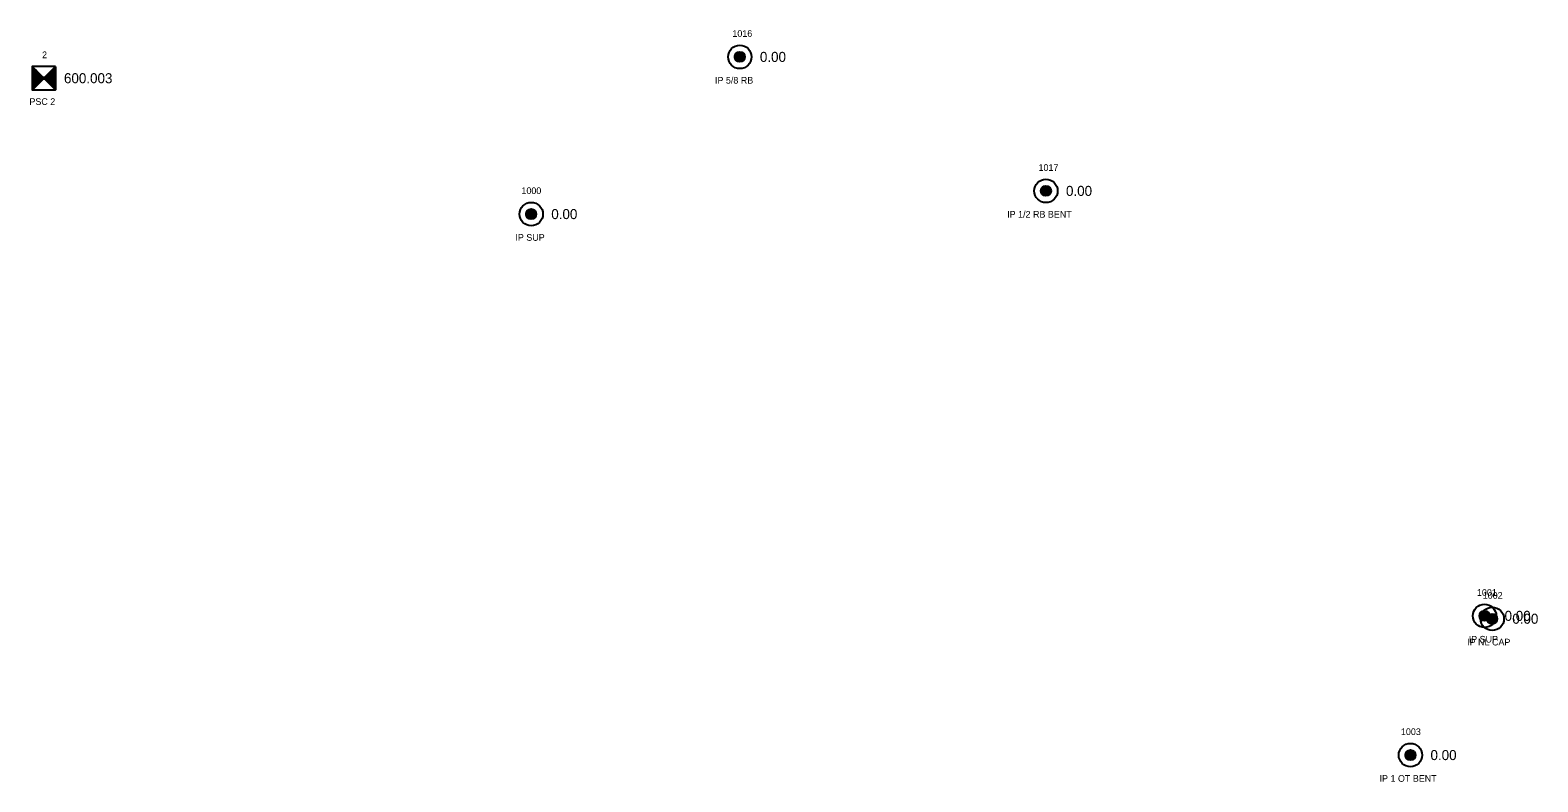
# Model space of a CAD drawing. Extents: x 1664393 to 1667175, y 987029 to 988607.
# Drawn here: x 1666338.4 to 1666564, y 987295.3 to 987407.9 of the extents above; entities that cross this region are included whole.
import ezdxf

# ---------------------------------------------------------------- set-up
doc = ezdxf.new("R2010")
doc.units = 0
for name, color, linetype in [('RD_EX_DV_Prop_txCode', 7, 'Continuous'), ('RD_EX_DV_PropPin', 7, 'Continuous'), ('RD_EX_TX_DV_Prop_ELEV', 7, 'Continuous'), ('RD_HC_Survey', 7, 'Continuous'), ('RD_HC_Survey_ELEV', 7, 'Continuous'), ('RD_HC_txCode', 7, 'Continuous'), ('RD_SMD_Locator', 7, 'Continuous')]:
    doc.layers.add(name, color=color, linetype=linetype)

msp = doc.modelspace()

# ---------------------------------------------------------------- linework, layer by layer
at = {"layer": 'RD_EX_DV_PropPin'}
for p, q in [((1666443.89, 987403.66), (1666443.89, 987404.05)), ((1666443.92, 987403.56), (1666443.92, 987404.15)), ((1666443.96, 987403.49), (1666443.96, 987404.23)), ((1666443.99, 987403.43), (1666443.99, 987404.28)), ((1666444.03, 987403.38), (1666444.03, 987404.33)), ((1666444.06, 987403.34), (1666444.06, 987404.37)), ((1666444.1, 987403.31), (1666444.1, 987404.41)), ((1666444.13, 987403.27), (1666444.13, 987404.44)), ((1666444.17, 987403.25), (1666444.17, 987404.47)), ((1666444.2, 987403.22), (1666444.2, 987404.49)), ((1666444.24, 987403.2), (1666444.24, 987404.51)), ((1666444.27, 987403.18), (1666444.27, 987404.53)), ((1666444.31, 987403.16), (1666444.31, 987404.55)), ((1666444.34, 987403.15), (1666444.34, 987404.56)), ((1666444.38, 987403.14), (1666444.38, 987404.58)), ((1666444.41, 987403.13), (1666444.41, 987404.59)), ((1666444.45, 987403.12), (1666444.45, 987404.6)), ((1666444.48, 987403.11), (1666444.48, 987404.6)), ((1666444.52, 987403.1), (1666444.52, 987404.61)), ((1666444.55, 987403.1), (1666444.55, 987404.61)), ((1666444.59, 987403.1), (1666444.59, 987404.62)), ((1666444.62, 987403.1), (1666444.62, 987404.62)), ((1666444.66, 987403.1), (1666444.66, 987404.62)), ((1666444.69, 987403.1), (1666444.69, 987404.61)), ((1666444.73, 987403.1), (1666444.73, 987404.61)), ((1666444.76, 987403.11), (1666444.76, 987404.6)), ((1666444.8, 987403.12), (1666444.8, 987404.6)), ((1666444.83, 987403.13), (1666444.83, 987404.59)), ((1666444.87, 987403.14), (1666444.87, 987404.58)), ((1666444.9, 987403.15), (1666444.9, 987404.56)), ((1666444.94, 987403.16), (1666444.94, 987404.55)), ((1666444.97, 987403.18), (1666444.97, 987404.53)), ((1666445.01, 987403.2), (1666445.01, 987404.51)), ((1666445.04, 987403.22), (1666445.04, 987404.49)), ((1666445.08, 987403.25), (1666445.08, 987404.47)), ((1666445.11, 987403.27), (1666445.11, 987404.44)), ((1666445.15, 987403.31), (1666445.15, 987404.41)), ((1666445.18, 987403.34), (1666445.18, 987404.37)), ((1666445.22, 987403.38), (1666445.22, 987404.33)), ((1666445.25, 987403.43), (1666445.25, 987404.28)), ((1666445.29, 987403.49), (1666445.29, 987404.23)), ((1666445.32, 987403.56), (1666445.32, 987404.15)), ((1666445.36, 987403.66), (1666445.36, 987404.05)), ((1666489.69, 987383.59), (1666489.69, 987383.98)), ((1666489.73, 987383.49), (1666489.73, 987384.08)), ((1666489.76, 987383.42), (1666489.76, 987384.15)), ((1666489.8, 987383.36), (1666489.8, 987384.21)), ((1666489.83, 987383.31), (1666489.83, 987384.26)), ((1666489.87, 987383.27), (1666489.87, 987384.3)), ((1666489.9, 987383.23), (1666489.9, 987384.34)), ((1666489.94, 987383.2), (1666489.94, 987384.37)), ((1666489.97, 987383.18), (1666489.97, 987384.4)), ((1666490.01, 987383.15), (1666490.01, 987384.42)), ((1666490.04, 987383.13), (1666490.04, 987384.44)), ((1666490.08, 987383.11), (1666490.08, 987384.46)), ((1666490.11, 987383.09), (1666490.11, 987384.48)), ((1666490.15, 987383.08), (1666490.15, 987384.49)), ((1666490.18, 987383.06), (1666490.18, 987384.51)), ((1666490.22, 987383.05), (1666490.22, 987384.52)), ((1666490.25, 987383.04), (1666490.25, 987384.53)), ((1666490.29, 987383.04), (1666490.29, 987384.53)), ((1666490.32, 987383.03), (1666490.32, 987384.54)), ((1666490.36, 987383.03), (1666490.36, 987384.54)), ((1666490.39, 987383.03), (1666490.39, 987384.55)), ((1666490.43, 987383.02), (1666490.43, 987384.55)), ((1666490.46, 987383.03), (1666490.46, 987384.55)), ((1666490.5, 987383.03), (1666490.5, 987384.54)), ((1666490.53, 987383.03), (1666490.53, 987384.54)), ((1666490.57, 987383.04), (1666490.57, 987384.53)), ((1666490.6, 987383.04), (1666490.6, 987384.53)), ((1666490.64, 987383.05), (1666490.64, 987384.52)), ((1666490.67, 987383.06), (1666490.67, 987384.51)), ((1666490.71, 987383.08), (1666490.71, 987384.49)), ((1666490.74, 987383.09), (1666490.74, 987384.48)), ((1666490.78, 987383.11), (1666490.78, 987384.46)), ((1666490.81, 987383.13), (1666490.81, 987384.44)), ((1666490.85, 987383.15), (1666490.85, 987384.42)), ((1666490.88, 987383.18), (1666490.88, 987384.4)), ((1666490.92, 987383.2), (1666490.92, 987384.37)), ((1666490.95, 987383.23), (1666490.95, 987384.34)), ((1666490.99, 987383.27), (1666490.99, 987384.3)), ((1666491.02, 987383.31), (1666491.02, 987384.26)), ((1666491.06, 987383.36), (1666491.06, 987384.21)), ((1666491.09, 987383.42), (1666491.09, 987384.15)), ((1666491.13, 987383.49), (1666491.13, 987384.08)), ((1666491.16, 987383.59), (1666491.16, 987383.98)), ((1666412.66, 987380.12), (1666412.66, 987380.51)), ((1666412.7, 987380.02), (1666412.7, 987380.61)), ((1666412.73, 987379.95), (1666412.73, 987380.69)), ((1666412.77, 987379.89), (1666412.77, 987380.74)), ((1666412.8, 987379.84), (1666412.8, 987380.79)), ((1666412.84, 987379.8), (1666412.84, 987380.83)), ((1666412.87, 987379.77), (1666412.87, 987380.87)), ((1666412.91, 987379.73), (1666412.91, 987380.9)), ((1666412.94, 987379.71), (1666412.94, 987380.93)), ((1666412.98, 987379.68), (1666412.98, 987380.95)), ((1666413.01, 987379.66), (1666413.01, 987380.97)), ((1666413.05, 987379.64), (1666413.05, 987380.99)), ((1666413.08, 987379.62), (1666413.08, 987381.01)), ((1666413.12, 987379.61), (1666413.12, 987381.02)), ((1666413.15, 987379.6), (1666413.15, 987381.04)), ((1666413.19, 987379.58), (1666413.19, 987381.05)), ((1666413.22, 987379.58), (1666413.22, 987381.06)), ((1666413.26, 987379.57), (1666413.26, 987381.06)), ((1666413.29, 987379.56), (1666413.29, 987381.07)), ((1666413.33, 987379.56), (1666413.33, 987381.07)), ((1666413.36, 987379.56), (1666413.36, 987381.08)), ((1666413.4, 987379.55), (1666413.4, 987381.08)), ((1666413.43, 987379.56), (1666413.43, 987381.08)), ((1666413.47, 987379.56), (1666413.47, 987381.07)), ((1666413.5, 987379.56), (1666413.5, 987381.07)), ((1666413.54, 987379.57), (1666413.54, 987381.06)), ((1666413.57, 987379.58), (1666413.57, 987381.06)), ((1666413.61, 987379.58), (1666413.61, 987381.05)), ((1666413.64, 987379.6), (1666413.64, 987381.04)), ((1666413.68, 987379.61), (1666413.68, 987381.02)), ((1666413.71, 987379.62), (1666413.71, 987381.01)), ((1666413.75, 987379.64), (1666413.75, 987380.99)), ((1666413.78, 987379.66), (1666413.78, 987380.97)), ((1666413.82, 987379.68), (1666413.82, 987380.95)), ((1666413.85, 987379.71), (1666413.85, 987380.93)), ((1666413.89, 987379.73), (1666413.89, 987380.9)), ((1666413.92, 987379.77), (1666413.92, 987380.87)), ((1666413.96, 987379.8), (1666413.96, 987380.83)), ((1666413.99, 987379.84), (1666413.99, 987380.79)), ((1666414.03, 987379.89), (1666414.03, 987380.74)), ((1666414.06, 987379.95), (1666414.06, 987380.69)), ((1666414.1, 987380.02), (1666414.1, 987380.61)), ((1666414.13, 987380.12), (1666414.13, 987380.51)), ((1666555.34, 987319.94), (1666555.34, 987320.33)), ((1666555.37, 987319.84), (1666555.37, 987320.43)), ((1666555.41, 987319.77), (1666555.41, 987320.51)), ((1666555.44, 987319.71), (1666555.44, 987320.56)), ((1666555.48, 987319.66), (1666555.48, 987320.61)), ((1666555.51, 987319.62), (1666555.51, 987320.65)), ((1666555.55, 987319.59), (1666555.55, 987320.69)), ((1666555.58, 987319.55), (1666555.58, 987320.72)), ((1666555.62, 987319.53), (1666555.62, 987320.75)), ((1666555.65, 987319.5), (1666555.65, 987320.77)), ((1666555.69, 987319.48), (1666555.69, 987320.79)), ((1666555.72, 987319.46), (1666555.72, 987320.81)), ((1666555.76, 987319.44), (1666555.76, 987320.83)), ((1666555.79, 987319.43), (1666555.79, 987320.84)), ((1666555.83, 987319.42), (1666555.83, 987320.86)), ((1666555.86, 987319.4), (1666555.86, 987320.87)), ((1666555.9, 987319.4), (1666555.9, 987320.88)), ((1666555.93, 987319.39), (1666555.93, 987320.88)), ((1666555.97, 987319.38), (1666555.97, 987320.89)), ((1666556, 987319.38), (1666556, 987320.89)), ((1666556.04, 987319.38), (1666556.04, 987320.9)), ((1666556.07, 987319.37), (1666556.07, 987320.9)), ((1666556.11, 987319.38), (1666556.11, 987320.9)), ((1666556.14, 987319.38), (1666556.14, 987320.89)), ((1666556.18, 987319.38), (1666556.18, 987320.89)), ((1666556.21, 987319.39), (1666556.21, 987320.88)), ((1666556.25, 987319.4), (1666556.25, 987320.88)), ((1666556.28, 987319.4), (1666556.28, 987320.87)), ((1666556.32, 987319.42), (1666556.32, 987320.86)), ((1666556.35, 987319.43), (1666556.35, 987320.84)), ((1666556.39, 987319.44), (1666556.39, 987320.83)), ((1666556.42, 987319.46), (1666556.42, 987320.81)), ((1666556.46, 987319.48), (1666556.46, 987320.79)), ((1666556.49, 987319.5), (1666556.49, 987320.77)), ((1666556.49, 987319.51), (1666556.49, 987319.9)), ((1666556.52, 987319.41), (1666556.52, 987320)), ((1666556.53, 987319.53), (1666556.53, 987320.75)), ((1666556.56, 987319.55), (1666556.56, 987320.72)), ((1666556.56, 987319.34), (1666556.56, 987320.07)), ((1666556.59, 987319.28), (1666556.59, 987320.13)), ((1666556.6, 987319.59), (1666556.6, 987320.69)), ((1666556.63, 987319.62), (1666556.63, 987320.65)), ((1666556.63, 987319.23), (1666556.63, 987320.18)), ((1666556.66, 987319.19), (1666556.66, 987320.22)), ((1666556.67, 987319.66), (1666556.67, 987320.61)), ((1666556.7, 987319.71), (1666556.7, 987320.56)), ((1666556.7, 987319.15), (1666556.7, 987320.26)), ((1666556.73, 987319.12), (1666556.73, 987320.29)), ((1666556.74, 987319.77), (1666556.74, 987320.51)), ((1666556.77, 987319.84), (1666556.77, 987320.43)), ((1666556.77, 987319.1), (1666556.77, 987320.31)), ((1666556.8, 987319.07), (1666556.8, 987320.34)), ((1666556.81, 987319.94), (1666556.81, 987320.33)), ((1666556.84, 987319.05), (1666556.84, 987320.36)), ((1666556.87, 987319.03), (1666556.87, 987320.38)), ((1666556.91, 987319.01), (1666556.91, 987320.4)), ((1666556.94, 987319), (1666556.94, 987320.41)), ((1666556.98, 987318.98), (1666556.98, 987320.43)), ((1666557.01, 987318.97), (1666557.01, 987320.44)), ((1666557.05, 987318.96), (1666557.05, 987320.45)), ((1666557.08, 987318.96), (1666557.08, 987320.45)), ((1666557.12, 987318.95), (1666557.12, 987320.46)), ((1666557.15, 987318.95), (1666557.15, 987320.46)), ((1666557.19, 987318.94), (1666557.19, 987320.47)), ((1666557.22, 987318.94), (1666557.22, 987320.47)), ((1666557.26, 987318.94), (1666557.26, 987320.47)), ((1666557.29, 987318.95), (1666557.29, 987320.46)), ((1666557.33, 987318.95), (1666557.33, 987320.46)), ((1666557.36, 987318.96), (1666557.36, 987320.45)), ((1666557.4, 987318.96), (1666557.4, 987320.45)), ((1666557.43, 987318.97), (1666557.43, 987320.44)), ((1666557.47, 987318.98), (1666557.47, 987320.43)), ((1666557.5, 987319), (1666557.5, 987320.41)), ((1666557.54, 987319.01), (1666557.54, 987320.4)), ((1666557.57, 987319.03), (1666557.57, 987320.38)), ((1666557.61, 987319.05), (1666557.61, 987320.36)), ((1666557.64, 987319.07), (1666557.64, 987320.34)), ((1666557.68, 987319.1), (1666557.68, 987320.31)), ((1666557.71, 987319.12), (1666557.71, 987320.29)), ((1666557.75, 987319.15), (1666557.75, 987320.26)), ((1666557.78, 987319.19), (1666557.78, 987320.22)), ((1666557.82, 987319.23), (1666557.82, 987320.18)), ((1666557.85, 987319.28), (1666557.85, 987320.13)), ((1666557.89, 987319.34), (1666557.89, 987320.07)), ((1666557.92, 987319.41), (1666557.92, 987320)), ((1666557.96, 987319.51), (1666557.96, 987319.9)), ((1666544.25, 987299.1), (1666544.25, 987299.49)), ((1666544.28, 987298.99), (1666544.28, 987299.59)), ((1666544.32, 987298.92), (1666544.32, 987299.66)), ((1666544.35, 987298.86), (1666544.35, 987299.72)), ((1666544.39, 987298.82), (1666544.39, 987299.77)), ((1666544.42, 987298.78), (1666544.42, 987299.81)), ((1666544.46, 987298.74), (1666544.46, 987299.84)), ((1666544.49, 987298.71), (1666544.49, 987299.87)), ((1666544.53, 987298.68), (1666544.53, 987299.9)), ((1666544.56, 987298.66), (1666544.56, 987299.93)), ((1666544.6, 987298.63), (1666544.6, 987299.95)), ((1666544.63, 987298.62), (1666544.63, 987299.97)), ((1666544.67, 987298.6), (1666544.67, 987299.98)), ((1666544.7, 987298.58), (1666544.7, 987300)), ((1666544.74, 987298.57), (1666544.74, 987300.01)), ((1666544.77, 987298.56), (1666544.77, 987300.02)), ((1666544.81, 987298.55), (1666544.81, 987300.03)), ((1666544.84, 987298.54), (1666544.84, 987300.04)), ((1666544.88, 987298.54), (1666544.88, 987300.05)), ((1666544.91, 987298.53), (1666544.91, 987300.05)), ((1666544.95, 987298.53), (1666544.95, 987300.05)), ((1666544.98, 987298.53), (1666544.98, 987300.05)), ((1666545.02, 987298.53), (1666545.02, 987300.05)), ((1666545.05, 987298.53), (1666545.05, 987300.05)), ((1666545.09, 987298.54), (1666545.09, 987300.05)), ((1666545.12, 987298.54), (1666545.12, 987300.04)), ((1666545.16, 987298.55), (1666545.16, 987300.03)), ((1666545.19, 987298.56), (1666545.19, 987300.02)), ((1666545.23, 987298.57), (1666545.23, 987300.01)), ((1666545.26, 987298.58), (1666545.26, 987300)), ((1666545.3, 987298.6), (1666545.3, 987299.98)), ((1666545.33, 987298.62), (1666545.33, 987299.97)), ((1666545.37, 987298.63), (1666545.37, 987299.95)), ((1666545.4, 987298.66), (1666545.4, 987299.93)), ((1666545.44, 987298.68), (1666545.44, 987299.9)), ((1666545.47, 987298.71), (1666545.47, 987299.87)), ((1666545.51, 987298.74), (1666545.51, 987299.84)), ((1666545.54, 987298.78), (1666545.54, 987299.81)), ((1666545.58, 987298.82), (1666545.58, 987299.77)), ((1666545.61, 987298.86), (1666545.61, 987299.72)), ((1666545.65, 987298.92), (1666545.65, 987299.66)), ((1666545.68, 987298.99), (1666545.68, 987299.59)), ((1666545.72, 987299.1), (1666545.72, 987299.49))]:
    msp.add_line(p, q, dxfattribs=at)
for centre, radius in [((1666444.62, 987403.86), 1.75), ((1666444.62, 987403.86), 0.761), ((1666490.43, 987383.79), 1.75), ((1666490.43, 987383.79), 0.761), ((1666413.4, 987380.32), 1.75), ((1666413.4, 987380.32), 0.761), ((1666556.07, 987320.14), 1.75), ((1666556.07, 987320.14), 0.761), ((1666557.22, 987319.7), 1.75), ((1666557.22, 987319.7), 0.761), ((1666544.98, 987299.29), 1.75), ((1666544.98, 987299.29), 0.761)]:
    msp.add_circle(centre, radius, dxfattribs=at)
at = {"layer": 'RD_HC_Survey'}
for p, q in [((1666338.72, 987402.42), (1666342.22, 987398.92)), ((1666342.22, 987402.42), (1666338.72, 987398.92)), ((1666338.75, 987402.39), (1666338.75, 987398.94)), ((1666338.77, 987402.37), (1666338.77, 987398.97)), ((1666338.8, 987402.34), (1666338.8, 987398.99)), ((1666338.82, 987402.32), (1666338.82, 987399.02)), ((1666338.85, 987402.29), (1666338.85, 987399.04)), ((1666338.87, 987402.27), (1666338.87, 987399.06)), ((1666338.9, 987402.24), (1666338.9, 987399.09)), ((1666338.92, 987402.22), (1666338.92, 987399.11)), ((1666338.95, 987402.19), (1666338.95, 987399.14)), ((1666338.97, 987402.17), (1666338.97, 987399.16)), ((1666338.99, 987402.14), (1666338.99, 987399.19)), ((1666339.02, 987402.12), (1666339.02, 987399.21)), ((1666339.04, 987402.09), (1666339.04, 987399.24)), ((1666339.07, 987402.07), (1666339.07, 987399.26)), ((1666339.09, 987402.04), (1666339.09, 987399.29)), ((1666339.12, 987402.02), (1666339.12, 987399.31)), ((1666339.14, 987402), (1666339.14, 987399.34)), ((1666339.17, 987401.97), (1666339.17, 987399.36)), ((1666339.19, 987401.95), (1666339.19, 987399.39)), ((1666339.22, 987401.92), (1666339.22, 987399.41)), ((1666339.24, 987401.9), (1666339.24, 987399.44)), ((1666339.27, 987401.87), (1666339.27, 987399.46)), ((1666339.29, 987401.85), (1666339.29, 987399.49)), ((1666339.32, 987401.82), (1666339.32, 987399.51)), ((1666339.34, 987401.8), (1666339.34, 987399.53)), ((1666339.37, 987401.77), (1666339.37, 987399.56)), ((1666339.39, 987401.75), (1666339.39, 987399.58)), ((1666339.42, 987401.72), (1666339.42, 987399.61)), ((1666339.44, 987401.7), (1666339.44, 987399.63)), ((1666339.47, 987401.67), (1666339.47, 987399.66)), ((1666339.49, 987401.65), (1666339.49, 987399.68)), ((1666339.51, 987401.62), (1666339.51, 987399.71)), ((1666339.54, 987401.6), (1666339.54, 987399.73)), ((1666339.56, 987401.57), (1666339.56, 987399.76)), ((1666339.59, 987401.55), (1666339.59, 987399.78)), ((1666339.61, 987401.53), (1666339.61, 987399.81)), ((1666339.64, 987401.5), (1666339.64, 987399.83)), ((1666339.66, 987401.48), (1666339.66, 987399.86)), ((1666339.69, 987401.45), (1666339.69, 987399.88)), ((1666339.71, 987401.43), (1666339.71, 987399.91)), ((1666339.74, 987401.4), (1666339.74, 987399.93)), ((1666339.76, 987401.38), (1666339.76, 987399.96)), ((1666339.79, 987401.35), (1666339.79, 987399.98)), ((1666339.81, 987401.33), (1666339.81, 987400.01)), ((1666339.84, 987401.3), (1666339.84, 987400.03)), ((1666339.86, 987401.28), (1666339.86, 987400.05)), ((1666339.89, 987401.25), (1666339.89, 987400.08)), ((1666339.91, 987401.23), (1666339.91, 987400.1)), ((1666339.94, 987401.2), (1666339.94, 987400.13)), ((1666339.96, 987401.18), (1666339.96, 987400.15)), ((1666339.98, 987401.15), (1666339.98, 987400.18)), ((1666340.01, 987401.13), (1666340.01, 987400.2)), ((1666340.03, 987401.1), (1666340.03, 987400.23)), ((1666340.06, 987401.08), (1666340.06, 987400.25)), ((1666340.08, 987401.05), (1666340.08, 987400.28)), ((1666340.11, 987401.03), (1666340.11, 987400.3)), ((1666340.13, 987401.01), (1666340.13, 987400.33)), ((1666340.16, 987400.98), (1666340.16, 987400.35)), ((1666340.18, 987400.96), (1666340.18, 987400.38)), ((1666340.21, 987400.93), (1666340.21, 987400.4)), ((1666340.23, 987400.91), (1666340.23, 987400.43)), ((1666340.26, 987400.88), (1666340.26, 987400.45)), ((1666340.28, 987400.86), (1666340.28, 987400.48)), ((1666340.31, 987400.83), (1666340.31, 987400.5)), ((1666340.33, 987400.81), (1666340.33, 987400.52)), ((1666340.36, 987400.78), (1666340.36, 987400.55)), ((1666340.38, 987400.76), (1666340.38, 987400.57)), ((1666340.41, 987400.73), (1666340.41, 987400.6)), ((1666340.54, 987400.73), (1666340.54, 987400.6)), ((1666340.56, 987400.76), (1666340.56, 987400.57)), ((1666340.59, 987400.78), (1666340.59, 987400.55)), ((1666340.61, 987400.81), (1666340.61, 987400.52)), ((1666340.64, 987400.83), (1666340.64, 987400.5)), ((1666340.66, 987400.86), (1666340.66, 987400.48)), ((1666340.69, 987400.88), (1666340.69, 987400.45)), ((1666340.71, 987400.91), (1666340.71, 987400.43)), ((1666340.74, 987400.93), (1666340.74, 987400.4)), ((1666340.76, 987400.96), (1666340.76, 987400.38)), ((1666340.79, 987400.98), (1666340.79, 987400.35)), ((1666340.81, 987401.01), (1666340.81, 987400.33)), ((1666340.84, 987401.03), (1666340.84, 987400.3)), ((1666340.86, 987401.05), (1666340.86, 987400.28)), ((1666340.89, 987401.08), (1666340.89, 987400.25)), ((1666340.91, 987401.1), (1666340.91, 987400.23)), ((1666340.94, 987401.13), (1666340.94, 987400.2)), ((1666340.96, 987401.15), (1666340.96, 987400.18)), ((1666340.99, 987401.18), (1666340.99, 987400.15)), ((1666341.01, 987401.2), (1666341.01, 987400.13)), ((1666341.03, 987401.23), (1666341.03, 987400.1)), ((1666341.06, 987401.25), (1666341.06, 987400.08)), ((1666341.08, 987401.28), (1666341.08, 987400.05)), ((1666341.11, 987401.3), (1666341.11, 987400.03)), ((1666341.13, 987401.33), (1666341.13, 987400.01)), ((1666341.16, 987401.35), (1666341.16, 987399.98)), ((1666341.18, 987401.38), (1666341.18, 987399.96)), ((1666341.21, 987401.4), (1666341.21, 987399.93)), ((1666341.23, 987401.43), (1666341.23, 987399.91)), ((1666341.26, 987401.45), (1666341.26, 987399.88)), ((1666341.28, 987401.48), (1666341.28, 987399.86)), ((1666341.31, 987401.5), (1666341.31, 987399.83)), ((1666341.33, 987401.53), (1666341.33, 987399.81)), ((1666341.36, 987401.55), (1666341.36, 987399.78)), ((1666341.38, 987401.57), (1666341.38, 987399.76)), ((1666341.41, 987401.6), (1666341.41, 987399.73)), ((1666341.43, 987401.62), (1666341.43, 987399.71)), ((1666341.46, 987401.65), (1666341.46, 987399.68)), ((1666341.48, 987401.67), (1666341.48, 987399.66)), ((1666341.5, 987401.7), (1666341.5, 987399.63)), ((1666341.53, 987401.72), (1666341.53, 987399.61)), ((1666341.55, 987401.75), (1666341.55, 987399.58)), ((1666341.58, 987401.77), (1666341.58, 987399.56)), ((1666341.6, 987401.8), (1666341.6, 987399.53)), ((1666341.63, 987401.82), (1666341.63, 987399.51)), ((1666341.65, 987401.85), (1666341.65, 987399.49)), ((1666341.68, 987401.87), (1666341.68, 987399.46)), ((1666341.7, 987401.9), (1666341.7, 987399.44)), ((1666341.73, 987401.92), (1666341.73, 987399.41)), ((1666341.75, 987401.95), (1666341.75, 987399.39)), ((1666341.78, 987401.97), (1666341.78, 987399.36)), ((1666341.8, 987402), (1666341.8, 987399.34)), ((1666341.83, 987402.02), (1666341.83, 987399.31)), ((1666341.85, 987402.04), (1666341.85, 987399.29)), ((1666341.88, 987402.07), (1666341.88, 987399.26)), ((1666341.9, 987402.09), (1666341.9, 987399.24)), ((1666341.93, 987402.12), (1666341.93, 987399.21)), ((1666341.95, 987402.14), (1666341.95, 987399.19)), ((1666341.98, 987402.17), (1666341.98, 987399.16)), ((1666342, 987402.19), (1666342, 987399.14)), ((1666342.02, 987402.22), (1666342.02, 987399.11)), ((1666342.05, 987402.24), (1666342.05, 987399.09)), ((1666342.07, 987402.27), (1666342.07, 987399.06)), ((1666342.1, 987402.29), (1666342.1, 987399.04)), ((1666342.12, 987402.32), (1666342.12, 987399.02)), ((1666342.15, 987402.34), (1666342.15, 987398.99)), ((1666342.17, 987402.37), (1666342.17, 987398.97)), ((1666342.2, 987402.39), (1666342.2, 987398.94)), ((1666340.43, 987400.71), (1666340.43, 987400.62)), ((1666340.46, 987400.68), (1666340.46, 987400.65)), ((1666340.49, 987400.68), (1666340.49, 987400.65)), ((1666340.51, 987400.71), (1666340.51, 987400.62))]:
    msp.add_line(p, q, dxfattribs=at)
msp.add_lwpolyline([(1666342.22, 987402.42), (1666338.72, 987402.42), (1666338.72, 987398.92), (1666342.22, 987398.92)], close=True, dxfattribs=at)
at = {"layer": 'RD_SMD_Locator'}
for centre in [(1666444.62, 987403.86), (1666340.47, 987400.67), (1666490.43, 987383.79), (1666413.4, 987380.32), (1666556.07, 987320.14), (1666557.22, 987319.7), (1666544.98, 987299.29)]:
    msp.add_circle(centre, 0.15, dxfattribs=at)

# ---------------------------------------------------------------- texts
at = {"layer": 'RD_EX_DV_Prop_txCode'}
for s, p in [('1016', (1666443.5, 987406.86)), ('IP 5/8 RB', (1666440.9, 987399.86)), ('1017', (1666489.32, 987386.79)), ('1000', (1666411.93, 987383.32)), ('IP 1/2 RB BENT', (1666484.63, 987379.79)), ('IP SUP', (1666411.03, 987376.32)), ('1001', (1666554.93, 987323.14)), ('1002', (1666555.8, 987322.71)), ('IP NL CAP', (1666553.47, 987315.71)), ('IP SUP', (1666553.7, 987316.14)), ('1003', (1666543.56, 987302.29)), ('IP 1 OT BENT', (1666540.36, 987295.29))]:
    msp.add_text(s, height=1, dxfattribs=at).set_placement(p)
at = {"layer": 'RD_EX_TX_DV_Prop_ELEV'}
for p in [(1666447.62, 987403.11), (1666493.43, 987383.04), (1666416.4, 987379.57), (1666559.07, 987319.39), (1666560.22, 987318.96), (1666547.98, 987298.54)]:
    msp.add_text('0.00', height=1.5, dxfattribs=at).set_placement(p)
at = {"layer": 'RD_HC_Survey_ELEV'}
msp.add_text('600.003', height=1.5, dxfattribs=at).set_placement((1666343.47, 987399.92))
at = {"layer": 'RD_HC_txCode'}
for s, p in [('2', (1666340.19, 987403.67)), ('PSC 2', (1666338.3, 987396.67))]:
    msp.add_text(s, height=1, dxfattribs=at).set_placement(p)

doc.saveas('drawing.dxf')
